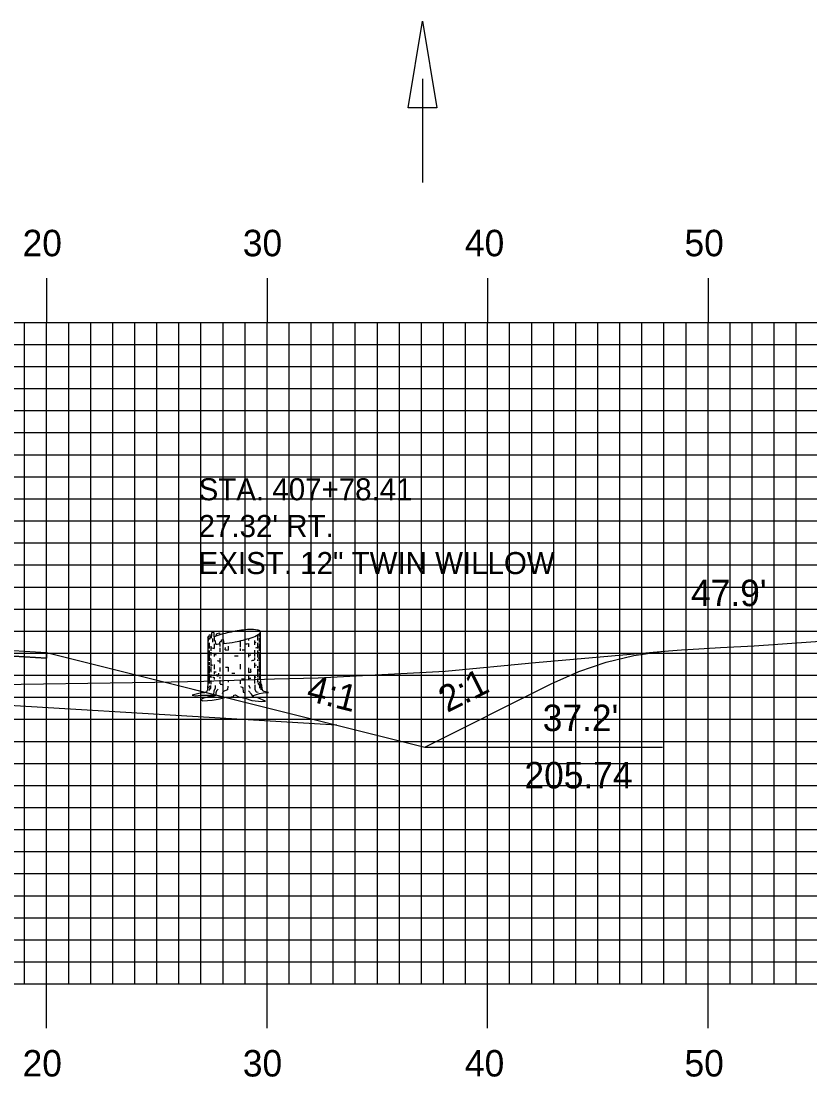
# Model space of a CAD drawing. Extents: x 852529 to 852872, y 364785 to 365005.
# Drawn here: x 852713.57 to 852749.35, y 364902.02 to 364949.9 of the extents above; entities that cross this region are included whole.
import ezdxf

# ---------------------------------------------------------------- set-up
doc = ezdxf.new("R2010")
doc.units = 0
for name, color, linetype in [('ANNOTATION', 7, 'Continuous'), ('D_Drainage_Ditch_Line', 7, 'Continuous'), ('D_Roadway_Edge_Shoulder', 7, 'Continuous'), ('D_Roadway_SlopeLines', 7, 'Continuous'), ('D_Roadway_SubGrade', 7, 'Continuous'), ('D_Text_Monospaced', 7, 'Continuous'), ('D_Text_Standard', 7, 'Continuous'), ('H_V ANNOTATION', 7, 'Continuous'), ('MAJOR', 7, 'Continuous'), ('MINOR', 7, 'Continuous'), ('PDRAIN', 7, 'Continuous'), ('S_Roadway_Centerline', 7, 'Continuous'), ('S_Trees_Decid_Pay', 7, 'Continuous')]:
    doc.layers.add(name, color=color, linetype=linetype)

msp = doc.modelspace()

# ---------------------------------------------------------------- linework, layer by layer
at = {"layer": 'D_Drainage_Ditch_Line'}
msp.add_line((852731.78, 364947.273), (852731.78, 364942.574), dxfattribs=at)
msp.add_lwpolyline([(852732.436, 364945.961), (852731.124, 364945.961), (852731.78, 364949.898)], close=True, dxfattribs=at)
at = {"layer": 'D_Roadway_Edge_Shoulder'}
msp.add_lwpolyline([(852706.731, 364921.742), (852714.731, 364921.262), (852714.731, 364921.012), (852706.731, 364921.492)], close=True, dxfattribs=at)
at = {"layer": 'D_Roadway_SlopeLines'}
for points in [[(852714.731, 364921.262), (852731.889, 364916.973)], [(852731.889, 364916.973), (852737.615, 364919.836), (852738.865, 364920.397), (852740.115, 364920.828), (852741.365, 364921.131), (852742.615, 364921.306)]]:
    msp.add_lwpolyline(points, dxfattribs=at)
at = {"layer": 'D_Roadway_SubGrade'}
msp.add_lwpolyline([(852682.731, 364920.682), (852674.731, 364920.522), (852674.731, 364922.772), (852674.731, 364923.022), (852674.731, 364922.772), (852682.731, 364922.932), (852694.731, 364922.212), (852706.731, 364921.492), (852714.731, 364921.012), (852714.731, 364921.262), (852727.889, 364917.973), (852706.731, 364919.242), (852694.731, 364919.962)], close=True, dxfattribs=at)
at = {"layer": 'MAJOR'}
for p, q in [((852714.731, 364938.237), (852714.731, 364936.233)), ((852724.731, 364938.237), (852724.731, 364936.233)), ((852734.731, 364938.237), (852734.731, 364936.233)), ((852744.731, 364938.237), (852744.731, 364936.233)), ((852554.731, 364936.233), (852834.731, 364936.233)), ((852554.731, 364936.233), (852834.731, 364936.233)), ((852714.731, 364906.233), (852714.731, 364936.233)), ((852724.731, 364906.233), (852724.731, 364936.233)), ((852734.731, 364906.233), (852734.731, 364936.233)), ((852744.731, 364906.233), (852744.731, 364936.233)), ((852554.731, 364931.233), (852834.731, 364931.233)), ((852554.731, 364926.233), (852834.731, 364926.233)), ((852554.731, 364921.233), (852834.731, 364921.233)), ((852554.731, 364916.233), (852834.731, 364916.233)), ((852554.731, 364911.233), (852834.731, 364911.233)), ((852554.731, 364906.233), (852834.731, 364906.233)), ((852554.731, 364906.233), (852834.731, 364906.233)), ((852714.731, 364904.229), (852714.731, 364906.233)), ((852724.731, 364904.229), (852724.731, 364906.233)), ((852734.731, 364904.229), (852734.731, 364906.233)), ((852744.731, 364904.229), (852744.731, 364906.233))]:
    msp.add_line(p, q, dxfattribs=at)
at = {"layer": 'MINOR'}
for p, q in [((852713.731, 364906.233), (852713.731, 364936.233)), ((852715.731, 364906.233), (852715.731, 364936.233)), ((852716.731, 364906.233), (852716.731, 364936.233)), ((852717.731, 364906.233), (852717.731, 364936.233)), ((852718.731, 364906.233), (852718.731, 364936.233)), ((852719.731, 364906.233), (852719.731, 364936.233)), ((852720.731, 364906.233), (852720.731, 364936.233)), ((852721.731, 364906.233), (852721.731, 364936.233)), ((852722.731, 364906.233), (852722.731, 364936.233)), ((852723.731, 364906.233), (852723.731, 364936.233)), ((852725.731, 364906.233), (852725.731, 364936.233)), ((852726.731, 364906.233), (852726.731, 364936.233)), ((852727.731, 364906.233), (852727.731, 364936.233)), ((852728.731, 364906.233), (852728.731, 364936.233)), ((852729.731, 364906.233), (852729.731, 364936.233)), ((852730.731, 364906.233), (852730.731, 364936.233)), ((852731.731, 364906.233), (852731.731, 364936.233)), ((852732.731, 364906.233), (852732.731, 364936.233)), ((852733.731, 364906.233), (852733.731, 364936.233)), ((852735.731, 364906.233), (852735.731, 364936.233)), ((852736.731, 364906.233), (852736.731, 364936.233)), ((852737.731, 364906.233), (852737.731, 364936.233)), ((852738.731, 364906.233), (852738.731, 364936.233)), ((852739.731, 364906.233), (852739.731, 364936.233)), ((852740.731, 364906.233), (852740.731, 364936.233)), ((852741.731, 364906.233), (852741.731, 364936.233)), ((852742.731, 364906.233), (852742.731, 364936.233)), ((852743.731, 364906.233), (852743.731, 364936.233)), ((852745.731, 364906.233), (852745.731, 364936.233)), ((852746.731, 364906.233), (852746.731, 364936.233)), ((852747.731, 364906.233), (852747.731, 364936.233)), ((852748.731, 364906.233), (852748.731, 364936.233)), ((852554.731, 364935.233), (852834.731, 364935.233)), ((852554.731, 364934.233), (852834.731, 364934.233)), ((852554.731, 364933.233), (852834.731, 364933.233)), ((852554.731, 364932.233), (852834.731, 364932.233)), ((852554.731, 364930.233), (852834.731, 364930.233)), ((852554.731, 364929.233), (852834.731, 364929.233)), ((852554.731, 364928.233), (852834.731, 364928.233)), ((852554.731, 364927.233), (852834.731, 364927.233)), ((852554.731, 364925.233), (852834.731, 364925.233)), ((852554.731, 364924.233), (852834.731, 364924.233)), ((852554.731, 364923.233), (852834.731, 364923.233)), ((852554.731, 364922.233), (852834.731, 364922.233)), ((852554.731, 364920.233), (852834.731, 364920.233)), ((852554.731, 364919.233), (852834.731, 364919.233)), ((852554.731, 364918.233), (852834.731, 364918.233)), ((852554.731, 364917.233), (852834.731, 364917.233)), ((852554.731, 364915.233), (852834.731, 364915.233)), ((852554.731, 364914.233), (852834.731, 364914.233)), ((852554.731, 364913.233), (852834.731, 364913.233)), ((852554.731, 364912.233), (852834.731, 364912.233)), ((852554.731, 364910.233), (852834.731, 364910.233)), ((852554.731, 364909.233), (852834.731, 364909.233)), ((852554.731, 364908.233), (852834.731, 364908.233)), ((852554.731, 364907.233), (852834.731, 364907.233))]:
    msp.add_line(p, q, dxfattribs=at)
at = {"layer": 'PDRAIN'}
msp.add_line((852731.889, 364916.973), (852742.66, 364916.973), dxfattribs=at)
at = {"layer": 'S_Roadway_Centerline'}
msp.add_lwpolyline([(852711.535, 364919.803), (852719.634, 364919.912), (852721.856, 364919.965), (852725.064, 364920.063), (852727.049, 364920.118), (852732.802, 364920.416), (852736.902, 364920.804), (852742.937, 364921.334), (852743.528, 364921.386), (852743.816, 364921.403), (852745.293, 364921.488), (852746.819, 364921.571), (852757.544, 364922.314)], dxfattribs=at)
at = {"layer": 'S_Trees_Decid_Pay'}
for p, q in [((852724.291, 364922.058), (852724.291, 364921.805)), ((852724.371, 364922.103), (852724.371, 364921.982)), ((852722.097, 364921.699), (852722.097, 364921.445)), ((852722.183, 364921.554), (852722.183, 364921.342)), ((852722.247, 364921.899), (852722.247, 364921.725)), ((852722.331, 364921.651), (852722.331, 364921.446)), ((852722.592, 364921.653), (852722.592, 364921.533)), ((852722.592, 364921.481), (852722.592, 364921.296)), ((852722.831, 364921.381), (852722.836, 364921.488)), ((852722.957, 364921.554), (852722.957, 364921.374)), ((852723.503, 364921.79), (852723.503, 364921.51)), ((852723.886, 364921.891), (852723.886, 364921.805)), ((852723.886, 364921.664), (852723.886, 364921.525)), ((852724.159, 364921.805), (852724.159, 364921.613)), ((852724.291, 364921.708), (852724.291, 364921.445)), ((852724.371, 364921.93), (852724.371, 364921.716)), ((852724.371, 364921.671), (852724.371, 364921.333)), ((852722.097, 364921.348), (852722.097, 364920.878)), ((852722.183, 364921.276), (852722.183, 364921.128)), ((852722.331, 364921.239), (852722.331, 364921.084)), ((852722.592, 364921.01), (852722.592, 364920.782)), ((852723.503, 364921.445), (852723.503, 364921.342)), ((852723.886, 364921.239), (852723.886, 364921.047)), ((852724.159, 364921.362), (852724.159, 364921.084)), ((852724.159, 364921.039), (852724.159, 364920.93)), ((852724.291, 364921.348), (852724.291, 364921.039)), ((852724.371, 364921.216), (852724.371, 364920.855)), ((852722.097, 364920.827), (852722.097, 364920.693)), ((852722.097, 364920.636), (852722.097, 364920.31)), ((852722.183, 364920.951), (852722.183, 364920.65)), ((852722.183, 364920.613), (852722.183, 364920.37)), ((852722.331, 364920.722), (852722.331, 364920.502)), ((852722.592, 364920.584), (852722.592, 364920.399)), ((852722.957, 364920.596), (852722.957, 364920.399)), ((852723.503, 364920.73), (852723.503, 364920.51)), ((852723.886, 364920.567), (852723.886, 364920.359)), ((852724.159, 364920.796), (852724.159, 364920.567)), ((852724.291, 364920.951), (852724.291, 364920.884)), ((852724.291, 364920.65), (852724.291, 364920.553)), ((852724.291, 364920.502), (852724.291, 364920.141)), ((852724.371, 364920.819), (852724.371, 364920.37)), ((852722.097, 364920.281), (852722.097, 364919.861)), ((852722.183, 364920.259), (852722.183, 364920.119)), ((852722.331, 364920.402), (852722.331, 364920.281)), ((852722.331, 364920.13), (852722.331, 364920.032)), ((852722.592, 364920.164), (852722.592, 364920.087)), ((852723.886, 364920.238), (852723.886, 364920.038)), ((852724.159, 364920.238), (852724.159, 364919.855)), ((852724.291, 364920.09), (852724.291, 364919.923)), ((852724.371, 364920.304), (852724.371, 364920.022)), ((852722.1, 364919.758), (852722.086, 364919.641)), ((852722.183, 364919.987), (852722.183, 364919.83)), ((852722.592, 364920.01), (852722.592, 364919.836)), ((852722.957, 364920.015), (852722.957, 364919.912)), ((852723.503, 364920.01), (852723.503, 364919.836)), ((852723.882, 364919.781), (852723.962, 364919.649))]:
    msp.add_line(p, q, dxfattribs=at)
for points in [[(852722.047, 364921.973), (852722.047, 364919.836), (852722.026, 364919.695), (852722.02, 364919.569), (852721.977, 364919.482), (852721.884, 364919.433), (852721.749, 364919.433), (852721.505, 364919.377), (852721.338, 364919.328), (852721.481, 364919.297), (852721.718, 364919.334), (852721.928, 364919.322), (852722.189, 364919.328), (852722.313, 364919.346), (852722.343, 364919.304), (852722.405, 364919.346), (852722.306, 364919.279), (852722.071, 364919.254), (852721.841, 364919.192), (852721.711, 364919.122), (852721.81, 364919.078), (852722.232, 364919.098), (852722.51, 364919.141), (852722.809, 364919.217), (852723.095, 364919.254), (852723.2, 364919.254), (852723.218, 364919.334), (852723.287, 364919.34), (852723.453, 364919.254), (852723.739, 364919.198), (852724.038, 364919.091), (852724.497, 364919.042), (852724.651, 364919.054), (852724.31, 364919.204), (852724.106, 364919.235), (852724.118, 364919.309), (852724.378, 364919.409), (852724.553, 364919.439), (852724.794, 364919.451), (852724.596, 364919.489), (852724.534, 364919.525), (852724.51, 364919.612), (852724.497, 364919.781), (852724.452, 364919.867), (852724.424, 364920.108), (852724.424, 364922.194)], [(852722.403, 364921.646), (852722.395, 364921.79), (852722.35, 364921.783), (852722.335, 364922.157), (852722.241, 364922.165), (852722.226, 364922.245), (852722.189, 364921.908), (852722.144, 364922.002), (852722.123, 364921.848), (852722.047, 364921.973), (852722.052, 364921.784)], [(852722.047, 364921.973), (852722.092, 364921.996), (852722.115, 364922.062), (852722.167, 364922.085), (852722.2, 364922.01)], [(852722.425, 364922.012), (852722.446, 364922.12), (852722.578, 364922.151), (852722.585, 364922.063)], [(852722.564, 364921.651), (852722.601, 364921.754), (852722.667, 364921.76), (852722.667, 364921.842), (852722.741, 364921.848), (852722.766, 364921.668)], [(852724, 364920.373), (852723.999, 364920.45), (852723.991, 364920.516)], [(852722.455, 364920.281), (852722.446, 364920.207), (852722.52, 364920.201), (852722.535, 364920.318)], [(852722.167, 364919.766), (852722.16, 364919.641), (852722.078, 364919.546)], [(852722.313, 364919.346), (852722.331, 364919.525), (852722.393, 364919.662), (852722.386, 364919.762)], [(852722.504, 364919.594), (852722.43, 364919.525), (852722.411, 364919.427), (852722.405, 364919.346)], [(852722.955, 364919.729), (852722.938, 364919.575), (852722.741, 364919.494), (852722.695, 364919.391)], [(852723.521, 364919.721), (852723.624, 364919.67), (852723.638, 364919.464), (852723.741, 364919.435)], [(852724.176, 364919.795), (852724.176, 364919.59), (852724.234, 364919.48), (852724.331, 364919.464)], [(852724.316, 364919.869), (852724.388, 364919.766), (852724.388, 364919.641)], [(852724.373, 364919.95), (852724.434, 364919.789), (852724.447, 364919.664), (852724.44, 364919.567)], [(852724.106, 364919.235), (852724.02, 364919.377), (852723.888, 364919.519)]]:
    msp.add_lwpolyline(points, dxfattribs=at)
for centre, radius, start, end in [((852722.856, 364920.786), 1.299, 107.8613, 113.3069), ((852724.336, 364916.192), 6.126, 100.7779, 107.8613), ((852724.336, 364916.192), 6.126, 93.6944, 100.7779), ((852724.025, 364921.009), 1.299, 78.2779, 93.6944), ((852723.615, 364923.167), 1.299, 287.8613, 303.2779), ((852724.192, 364921.812), 0.48, 69.9843, 78.2779), ((852724.064, 364922.482), 0.48, 303.2779, 311.5714), ((852724.3, 364922.108), 0.164, 55.7779, 69.9843), ((852724.274, 364922.246), 0.164, 311.5714, 325.7779), ((852724.332, 364922.155), 0.107, 45.9547, 55.7779), ((852724.362, 364922.186), 0.0645, 33.2779, 45.9547), ((852724.321, 364922.214), 0.107, 325.7779, 335.6011), ((852724.37, 364922.191), 0.0544, 22.46, 33.2779), ((852724.36, 364922.196), 0.0645, 335.6011, 348.2779), ((852724.377, 364922.194), 0.0467, 10.7779, 22.46), ((852724.377, 364922.194), 0.0467, 359.0957, 10.7779), ((852724.369, 364922.194), 0.0544, 348.2779, 359.0957), ((852722.094, 364921.605), 0.0476, 180, 191.6815), ((852722.102, 364921.607), 0.0554, 191.6815, 202.5), ((852722.112, 364921.611), 0.0657, 202.5, 215.1737), ((852722.147, 364921.636), 0.109, 215.1737, 225), ((852722.188, 364921.676), 0.166, 225, 239.1924), ((852722.659, 364922.695), 1.292, 250.6119, 255.2856), ((852722.445, 364922.945), 1.299, 268.1289, 273.6944), ((852722.134, 364927.761), 6.126, 273.6944, 274.0246), ((852722.134, 364927.761), 6.126, 275.9147, 280.7779), ((852722.134, 364927.761), 6.126, 280.7779, 287.8613), ((852723.236, 364927.544), 5.916, 274.9515, 276.3087), ((852723.812, 364922.956), 1.292, 285.5651, 289.0916), ((852723.811, 364922.695), 1.292, 288.0829, 292.5), ((852724.12, 364921.949), 0.484, 297.4162, 300.8076), ((852724.283, 364921.676), 0.166, 300.8076, 315), ((852724.284, 364921.937), 0.166, 301.67, 315), ((852724.324, 364921.636), 0.109, 315, 324.8263), ((852724.325, 364921.896), 0.109, 315, 324.8263), ((852724.359, 364921.611), 0.0657, 324.8263, 337.5), ((852724.36, 364921.871), 0.0657, 324.8263, 337.5), ((852724.369, 364921.607), 0.0554, 337.5, 348.3185), ((852724.37, 364921.868), 0.0554, 337.5, 348.3185), ((852722.094, 364921.084), 0.0476, 180, 191.6815), ((852722.102, 364921.086), 0.0554, 191.6815, 202.5), ((852722.112, 364921.09), 0.0657, 202.5, 215.1737), ((852722.147, 364921.115), 0.109, 215.1737, 225), ((852722.188, 364921.155), 0.166, 225, 239.1924), ((852722.188, 364921.413), 0.166, 237.0378, 239.1924), ((852722.35, 364921.686), 0.484, 239.1924, 247.5), ((852722.35, 364921.428), 0.484, 239.1924, 245.7725), ((852722.659, 364922.432), 1.292, 247.5, 248.3537), ((852722.659, 364922.175), 1.292, 247.5, 248.4842), ((852722.659, 364922.432), 1.292, 255.2856, 259.2632), ((852723.235, 364927.283), 5.916, 266.0776, 267.3043), ((852723.235, 364927.02), 5.916, 270.1162, 271.7708), ((852723.235, 364927.283), 5.916, 273.5382, 274.8924), ((852723.235, 364927.02), 5.916, 276.3184, 277.1546), ((852723.811, 364922.432), 1.292, 277.1546, 278.3662), ((852723.811, 364922.432), 1.292, 291.8071, 292.5), ((852724.12, 364921.686), 0.484, 292.5, 300.8076), ((852724.12, 364921.428), 0.484, 294.6372, 300.8076), ((852724.283, 364921.413), 0.166, 300.8076, 301.6001), ((852724.283, 364921.155), 0.166, 300.8076, 315), ((852724.324, 364921.115), 0.109, 315, 324.8263), ((852724.359, 364921.09), 0.0657, 324.8263, 337.5), ((852724.369, 364921.086), 0.0554, 337.5, 348.3185), ((852722.094, 364920.827), 0.0476, 180, 191.6815), ((852722.094, 364920.561), 0.0476, 180, 191.6815), ((852722.102, 364920.828), 0.0554, 191.6815, 202.5), ((852722.102, 364920.563), 0.0554, 191.6815, 202.5), ((852722.112, 364920.832), 0.0657, 202.5, 215.1737), ((852722.112, 364920.567), 0.0657, 202.5, 215.1737), ((852722.147, 364920.857), 0.109, 215.1737, 225), ((852722.147, 364920.592), 0.109, 215.1737, 225), ((852722.188, 364920.898), 0.166, 225, 239.1924), ((852722.188, 364920.632), 0.166, 225, 239.1924), ((852722.659, 364921.917), 1.292, 247.5, 251.799), ((852722.659, 364922.175), 1.292, 261.8726, 262.8454), ((852723.235, 364926.762), 5.916, 262.8454, 263.7595), ((852723.235, 364926.505), 5.916, 266.2721, 267.3043), ((852723.811, 364922.175), 1.292, 279.2565, 285.6105), ((852723.811, 364921.917), 1.292, 285.6105, 290.1001), ((852724.283, 364920.898), 0.166, 302.0694, 315), ((852724.324, 364920.857), 0.109, 315, 324.8263), ((852724.359, 364920.832), 0.0657, 324.8263, 337.5), ((852724.369, 364920.828), 0.0554, 337.5, 348.3185), ((852724.369, 364920.563), 0.0554, 337.5, 348.3185), ((852722.094, 364920.032), 0.0476, 180, 191.6815), ((852722.102, 364920.034), 0.0554, 191.6815, 202.5), ((852722.35, 364920.905), 0.484, 239.1924, 247.5), ((852722.35, 364920.633), 0.484, 242.734, 247.5), ((852722.659, 364921.652), 1.292, 247.5, 248.3537), ((852722.659, 364921.38), 1.292, 251.3664, 255.2856), ((852722.659, 364921.652), 1.292, 255.2856, 259.2463), ((852723.235, 364926.239), 5.916, 268.9207, 270), ((852723.235, 364926.239), 5.916, 270, 270.2757), ((852723.235, 364925.968), 5.916, 273.2637, 274.461), ((852723.235, 364926.239), 5.916, 276.3184, 277.1546), ((852723.235, 364925.968), 5.916, 276.3184, 277.1546), ((852723.811, 364921.652), 1.292, 277.1546, 278.3795), ((852723.811, 364921.38), 1.292, 277.1546, 278.3662), ((852723.811, 364921.38), 1.292, 285.6105, 289.1534), ((852724.12, 364920.905), 0.484, 292.5, 300.8076), ((852724.283, 364920.632), 0.166, 300.8076, 302.0694), ((852724.283, 364920.361), 0.166, 302.0694, 315), ((852724.324, 364920.32), 0.109, 315, 324.8263), ((852724.359, 364920.295), 0.0657, 324.8263, 337.5), ((852724.369, 364920.291), 0.0554, 337.5, 348.3185), ((852722.112, 364920.038), 0.0657, 202.5, 215.1737), ((852722.147, 364920.063), 0.109, 215.1737, 225), ((852722.188, 364920.103), 0.166, 225, 239.1924), ((852722.35, 364920.376), 0.484, 239.1924, 247.5), ((852722.659, 364921.122), 1.292, 247.5, 248.3537), ((852723.235, 364925.71), 5.916, 263.7831, 264.7656), ((852723.82, 364921.126), 1.292, 291.3696, 292.0604), ((852724.12, 364920.376), 0.484, 292.5, 296.5499)]:
    msp.add_arc(centre, radius, start, end, dxfattribs=at)

# ---------------------------------------------------------------- texts
at = {"layer": 'ANNOTATION'}
for s, rotation, p in [('4:1', 345.9638, (852726.463, 364919.096)), ('2:1', 26.5651, (852732.897, 364918.513))]:
    msp.add_text(s, height=1.2, rotation=rotation, dxfattribs=at).set_placement(p)
for s, p in [("37.2'", (852737.231, 364917.699)), ('205.74', (852736.401, 364915.099))]:
    msp.add_text(s, height=1.2, dxfattribs=at).set_placement(p)
at = {"layer": 'D_Text_Monospaced'}
for s, height, p in [('STA. 407+78.41', 0.99996, (852721.624, 364928.166)), ("27.32' RT.", 1, (852721.624, 364926.498)), ('EXIST. 12" TWIN WILLOW ', 0.99996, (852721.624, 364924.818))]:
    msp.add_text(s, height=height, dxfattribs=at).set_placement(p)
at = {"layer": 'D_Text_Standard'}
msp.add_text("47.9'", height=1.2, dxfattribs=at).set_placement((852743.957, 364923.365))
at = {"layer": 'H_V ANNOTATION'}
for s, p in [('20', (852713.639, 364939.233)), ('30', (852723.628, 364939.233)), ('40', (852733.703, 364939.233)), ('50', (852743.66, 364939.233)), ('20', (852713.639, 364902.033)), ('30', (852723.628, 364902.033)), ('40', (852733.703, 364902.033)), ('50', (852743.66, 364902.033))]:
    msp.add_text(s, height=1.2, dxfattribs=at).set_placement(p)

doc.saveas('drawing.dxf')
